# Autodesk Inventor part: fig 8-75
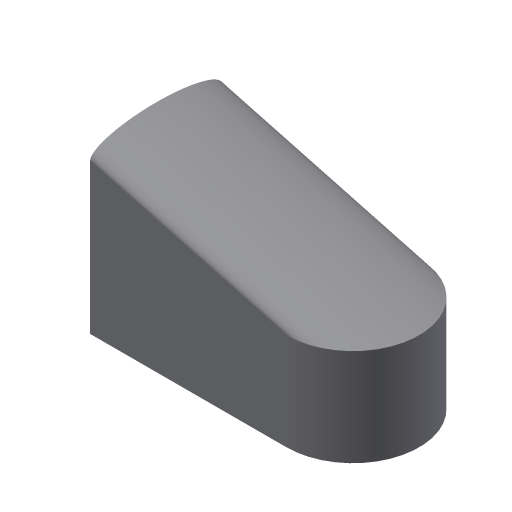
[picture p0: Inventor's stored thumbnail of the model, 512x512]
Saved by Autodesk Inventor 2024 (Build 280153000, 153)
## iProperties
Shininess: 77.0
Length Units: 11269
Angle Units: 11279
Time Units: 11290
Mass Units: 11283
Length Display Precision: 3
Angle Display Precision: 2
Created: 2002-01
Part Number: fig 8-75
Document SubType Name: Modeling
Designer: ***
Density: 1 g/cm^3
Material: Generic
Appearance: Default
Density: 0.0
Volumn: 0.0
Area: 0.0
PropertySet Name: Model Information
Control State: 0
Master: False
Checked Out: False
Author: ***
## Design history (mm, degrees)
sketch "Sketch2"
  geometry: L1 (-36.915, 19.946)-(-36.915, -14.161); L2 (-36.915, -14.161)-(13.729, -14.161); L3 (13.729, 19.946)-(-36.915, 19.946); A1 r 17.054 centre (13.729, 2.893) between (13.729, -14.161) and (13.729, 19.946)
  constraints: 6 end point, 2 point on circle, 2 tangent, 1 centre point, 1 parallel, 1 perpendicular, 1 vertical
extrude "Extrusion2" new body sketch "Sketch2" distance "d6" = 25; taper "d7" = 0 deg
feature "FaceDraft9" dims angle "d15" = 15 deg
body "Solid1"
